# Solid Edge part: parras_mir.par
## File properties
Author: Kasutaja
Template: Ansi Inch Part.par
Last saved by: Kasutaja
Revision: 6
Application: Solid Edge
Accuracy: 0,990
Username: Kasutaja
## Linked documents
parras.par
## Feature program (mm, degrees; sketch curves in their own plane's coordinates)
part copy "CopiedPart_1"
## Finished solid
Body 1: solid body, 11 faces, 20 edges, 8 vertices.
  Faces by surface: cylinder 4, plane 3, spline 3, offset 1
  Edges by curve: intersection 12, curve on surface 5, line 2, spline 1
Bounding box of the edges (mm; curved faces can reach further): 632.055 x 97.729 x 109.495, from (-275.7609, 4.0001, 5.5) to (356.294, 101.7292, 114.9947).
Cylindrical faces by radius (mm): R3 x4
Planar faces by outward normal: +z 1, -y 1, -z 1
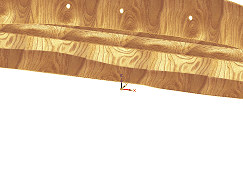
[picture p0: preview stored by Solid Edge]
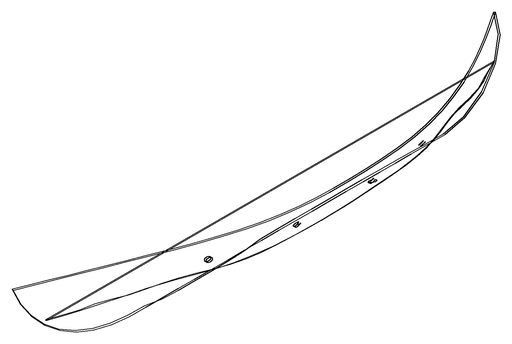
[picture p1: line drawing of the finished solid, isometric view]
